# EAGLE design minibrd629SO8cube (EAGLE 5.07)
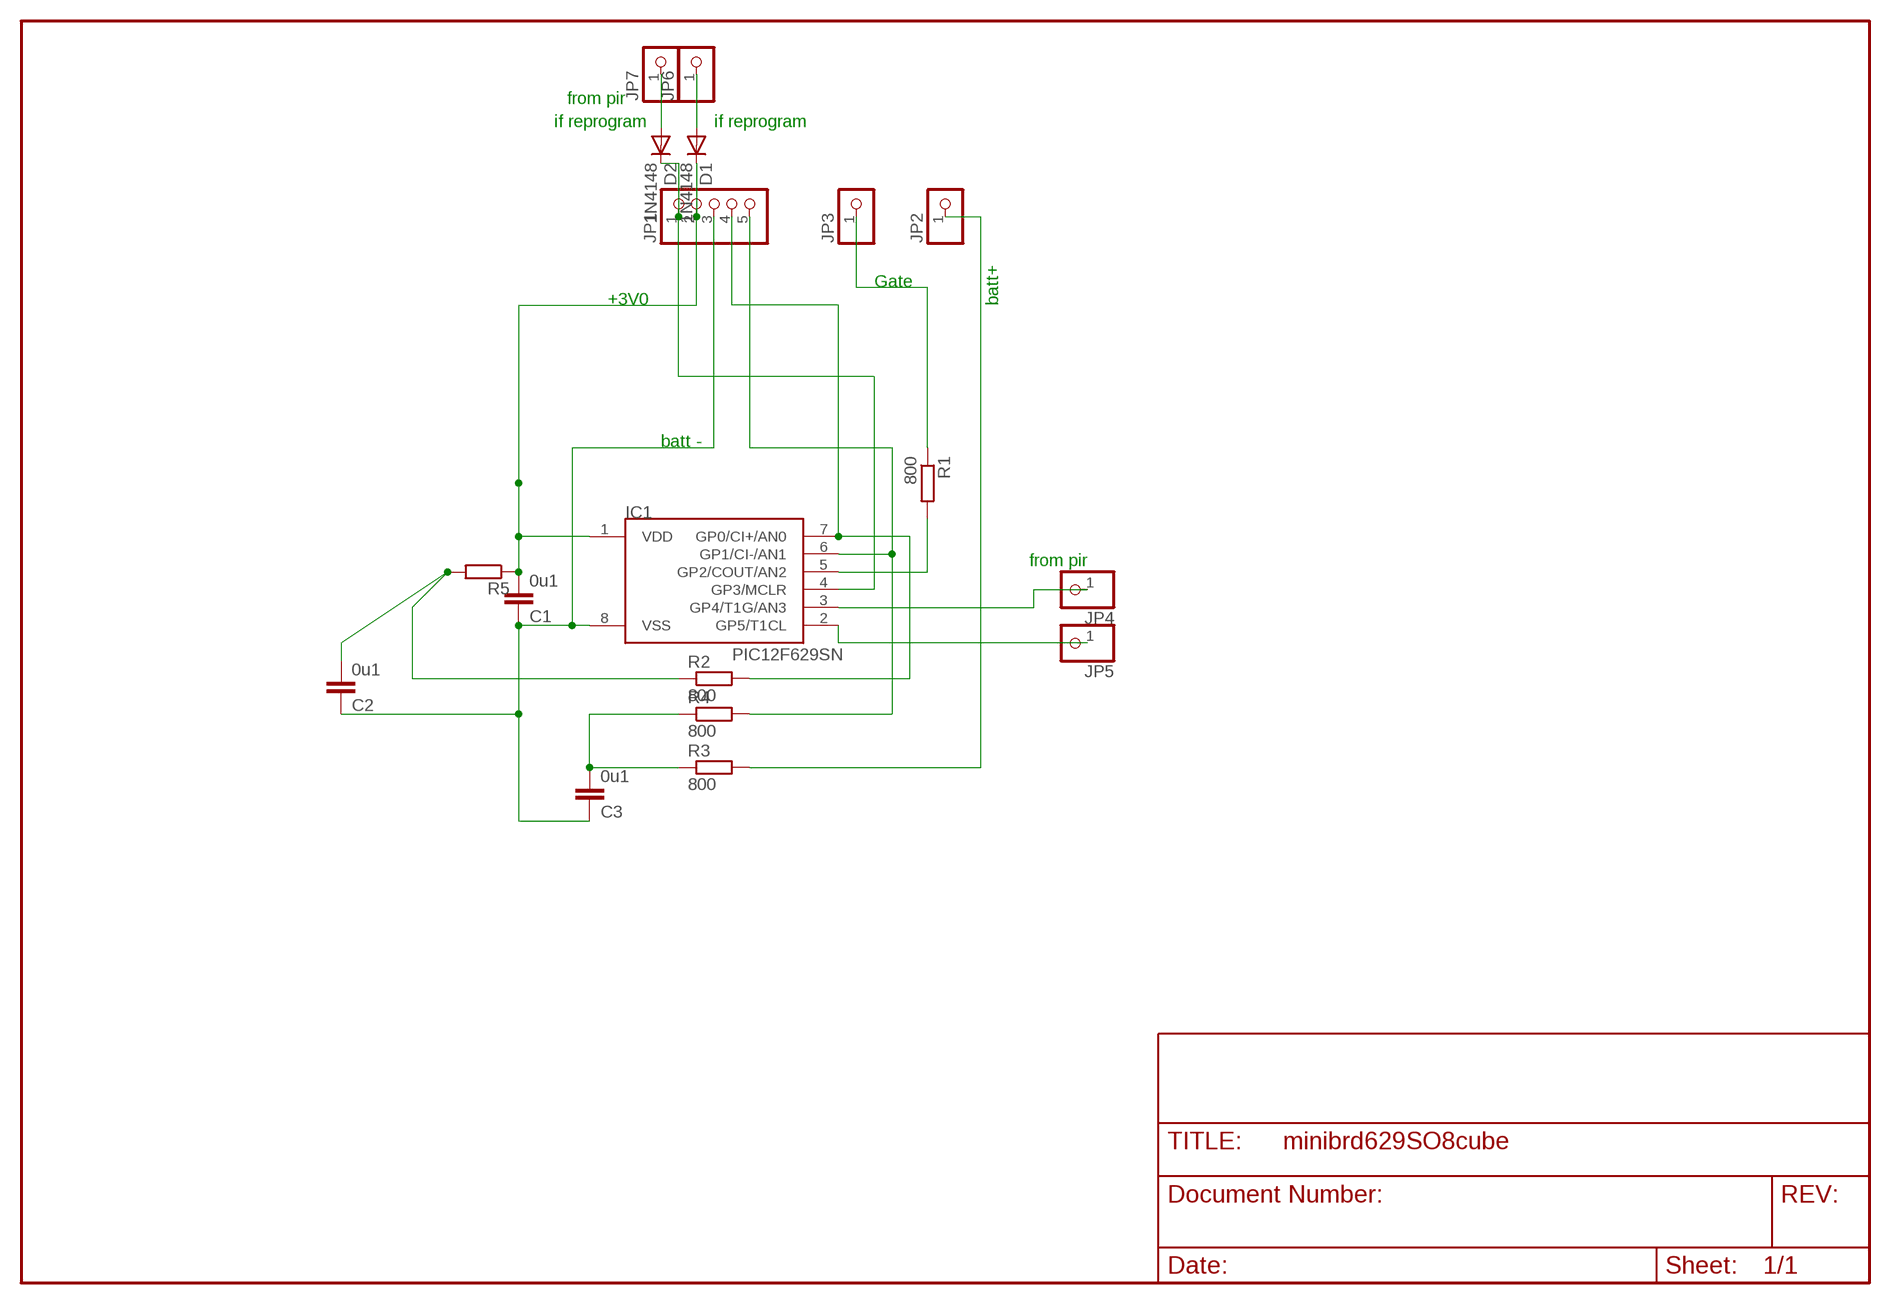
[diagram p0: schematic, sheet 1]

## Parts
C1  0u1  C-EUC1206  [C1206]
C2  0u1  C-EUC1206  [C1206]
C3  0u1  C-EUC1206  [C1206]
D1  1N4148  [DO35-10]
D2  1N4148  [DO35-10]
IC1  PIC12F629SN  [SO-08]
JP1  PINHD-1X5  [1X05]
JP2  PINHD-1X1  [1X01]
JP3  PINHD-1X1  [1X01]
JP4  PINHD-1X1  [1X01]
JP5  PINHD-1X1  [1X01]
JP6  PINHD-1X1  [1X01]
JP7  PINHD-1X1  [1X01]
R1  800  R-EU_M1206  [M1206]
R2  800  R-EU_M1206  [M1206]
R3  800  R-EU_M1206  [M1206]
R4  800  R-EU_M1206  [M1206]
R5  R-EU_0613/5V  [P0613V]

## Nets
N$1: IC1.5(GP2/COUT/AN2) R1.2
N$2: D2.A JP7.1
N$3: D1.A JP6.1
N$4: IC1.7(GP0/CI+/AN0) JP1.4 R2.2
N$5: JP3.1 R1.1
N$6: C2.2 R2.1 R5.2
N$7: C3.2 R3.1 R4.1
N$8: IC1.6(GP1/CI-/AN1) JP1.5 R4.2
N$13: IC1.3(GP4/T1G/AN3) JP4.1
N$14: IC1.2(GP5/T1CL) JP5.1
PIR: D2.C IC1.4(GP3/MCLR) JP1.1
V3: C1.2 D1.C IC1.1(VDD) JP1.2 R5.1
V+: JP2.1 R3.2
V-: C1.1 C2.1 C3.1 IC1.8(VSS) JP1.3

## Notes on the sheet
- from pir
- if reprogram | if reprogram
- Gate
- +3V0 | batt+
- batt -
- from pir

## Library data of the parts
C1-C3 = rcl:C-EU: CAPACITOR, European symbol
D1 D2 = diode-1:1N4148: DIODE
IC1 = microchip-3:PIC12F6*: uPC nW 1k Program Flash memory 2x Timer Comparator 10b A/D converter/ 4xIN
JP1 = pinhead:PINHD-1X5: PIN HEADER
JP2-JP7 = pinhead:PINHD-1X1: PIN HEADER
R1-R5 = rcl:R-EU_: RESISTOR, European symbol

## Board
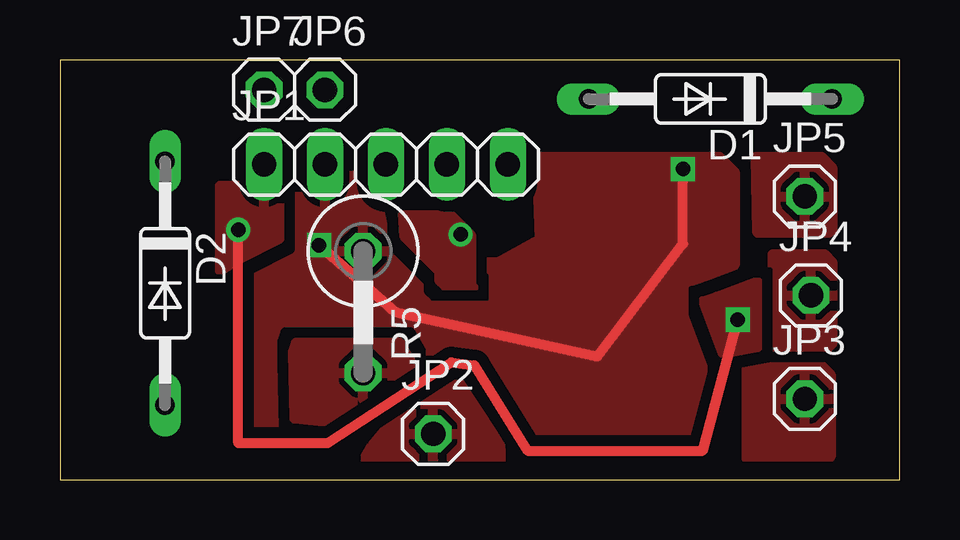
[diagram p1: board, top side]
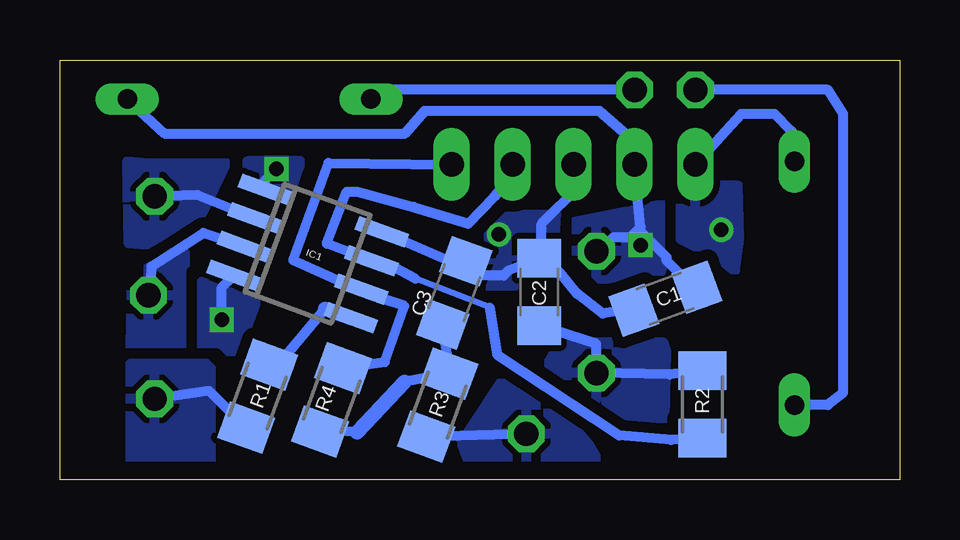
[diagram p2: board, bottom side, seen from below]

Size 35 x 17.5 mm. Coordinates in mm from the lower left corner, seen from the top.
Outline: 0,0 35,0 35,17.5 0,17.5 0,0
Copper layers (1*16): Top 0.035mm / dielectric 1.5mm / Bottom 0.035mm
Design rules "default *": minimum track width 10mil, minimum drill 24mil, track to track 18mil, track to pad 18mil, pad to pad 8mil, via to via 8mil, smd to smd 8mil, copper to edge 30mil, drill to drill 8mil, minimum pad ring 10mil, minimum via ring 8mil, stop-mask expansion 4mil, vias tented up to drill 0mil, thermal gap 10mil

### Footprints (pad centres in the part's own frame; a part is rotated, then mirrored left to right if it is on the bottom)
C1206 = smd 1.6 x 1.8: 1 -1.4,0; 2 1.4,0
DO35-10 = drill 0.813 long: A 5.08,0; C -5.08,0
SO-08 = smd 0.6 x 2.2: 1 -1.905,-2.6; 2 -0.635,-2.6; 3 0.635,-2.6; 4 1.905,-2.6; 5 1.905,2.6; 6 0.635,2.6; 7 -0.635,2.6; 8 -1.905,2.6
1X05 = drill 1.016 long: 1 -5.08,0; 2 -2.54,0; 3 0,0; 4 2.54,0; 5 5.08,0
1X01 = drill 1.016 octagon: 1 0,0
M1206 = smd 1.6 x 2: 1 -1.4,0; 2 1.4,0
P0613V = drill 1.016 octagon: 1 -2.54,0; 2 2.54,0

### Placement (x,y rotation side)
C1  9.76,7.54 20 bottom
C2  15.02,7.82 270 bottom
C3  18.56,7.79 250 bottom
D1  27.11,15.88 180 top
D2  4.38,8.19 270 top
IC1  24.67,9.43 250 bottom
JP1  13.59,13.14 0 top
JP2  15.56,1.91 0 top
JP3  31.05,3.37 0 top
JP4  31.31,7.68 0 top
JP5  31.05,11.81 0 top
JP6  11.05,16.26 0 top
JP7  8.51,16.26 0 top
R1  26.76,3.47 70 bottom
R2  8.22,3.14 270 bottom
R3  19.25,3.1 250 bottom
R4  23.67,3.33 70 bottom
R5  12.64,6.99 270 top

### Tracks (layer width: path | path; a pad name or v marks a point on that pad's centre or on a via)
N$1
  Bottom 0.406: R1.2 25.97,4.7 23.94,7.11
  Bottom 0.61: 23.94,7.11 IC1.5
N$2
  Bottom 0.406: D2.A 2.98,3.11 2.35,3.62 2.35,15.24 2.98,16.26 JP7.1
N$3
  Bottom 0.406: JP6.1 21.34,16.26 21.34,16.13 D1.A
N$4
  Bottom 0.254: 17.08,7.18 20.19,8.38
  Bottom 0.406: JP1.4 16,12.83 16.89,11.81 17.97,10.67 20.26,11.37 22.61,12 23.05,12 23.88,9.84 IC1.7 21.91,9.08 21.02,8.83 20.19,8.38 | 17.08,7.18 16.76,5.21 11.68,1.84 9.53,1.65 R2.2
N$5
  Bottom 0.406: R1.1 28.77,3.69 JP3.1
  pour Bottom: 28.89,4.83 32.07,4.83 32.07,0.76 28.7,0.76 28.7,4.64
  pour Top (rank 2): 28.64,4.7 31.81,4.7 32.13,4.38 32.13,0.95 31.94,0.76 28.7,0.76 28.64,0.83
N$6
  Bottom 0.406: R2.1 9.59,4.38 R5.2 12.64,5.65 C2.2
  pour Bottom: 9.84,5.71 14.16,5.71 14.73,4.7 10.99,2.41 9.78,2.54 9.72,5.33
  pour Top: 9.84,5.71 14.16,5.71 14.73,4.7 10.99,2.41 9.78,2.54 9.72,5.33
N$7
  Bottom 0.406: C3.2 18.73,4.32 R3.1 20.64,4.06 | R4.1 24,2.1 22.61,1.97
  Bottom 0.61: 20.64,4.06 22.61,1.97
N$8
  Bottom 0.406: JP1.5 23.81,13.21 25.27,9.14 23.05,8.13 22.54,7.87 | 22.54,7.87 IC1.6 | 22.54,7.87 20.64,7.24 21.46,4.89 23.3,4.64 R4.2
N$13
  Bottom 0.406: IC1.3 29.02,10.29 31.18,8.89 JP4.1
  pour Bottom (rank 3): 30.61,9.14 32,8.51 32.07,5.52 29.78,5.52 29.78,9.46
  pour Top (rank 3): 29.72,9.4 31.88,9.4 32.19,9.08 32.19,5.65 32.07,5.52 29.72,5.52 29.65,5.59
N$14
  Bottom 0.406: IC1.2 29.27,11.87 31.18,11.81 JP5.1
  pour Bottom: 28.07,13.21 29.08,11.11 31.43,9.78 32.13,9.84 32.19,13.27 31.24,13.21
  pour Top: 29.02,13.46 31.75,13.46 32.19,13.02 32.19,10.41 32.07,10.29 29.08,10.29
PIR  (via drill 0.6)
  Top 0.406: v7.43,10.41 7.43,1.52 11.18,1.52 16.32,4.89 17.27,4.76 19.49,1.21 26.8,1.21 v28.26,6.67
  Bottom 0.406: IC1.4 27.77,8.49 28.26,8 v28.26,6.67 | D2.C 4.51,14.54 5.21,15.24 6.6,15.24 JP1.1
  pour Bottom (rank 2): 26.8,7.43 27.62,5.27 29.08,5.52 29.08,8.26 27.37,7.62
  pour Bottom: 6.73,12.26 9.14,12.32 9.14,10.03 7.49,9.21 6.86,8.7 6.67,10.03
  pour Top: 26.8,7.43 27.62,5.27 29.08,5.52 29.08,8.26 27.37,7.62
  pour Top: 6.67,12.26 9.14,12.32 9.14,10.03 7.49,9.21 6.67,8.7
V3  (via drill 0.6)
  Top 0.406: v25.97,12.95 25.97,9.84 22.42,5.14 13.97,6.99 v10.79,9.78
  Bottom 0.406: IC1.1 26.46,12.46 v25.97,12.95 | 10.89,10.45 10.99,10.35 | 10.99,10.35 11.24,10.1 11.94,10.1 12.64,9.4 R5.1 | 10.89,10.45 10.8,10.54 JP1.2 11.05,14.1 12.51,15.37 19.81,15.37 20.64,14.41 30.61,14.41 D1.C | C1.2 8.59,8.02 9.72,9.14 9.72,9.27 10.89,10.45 | 10.89,10.45 | v10.79,9.78 10.79,10.16 10.99,10.35
  pour Bottom (rank 2): 25.34,12.13 24.96,13.27 27.18,13.27 27.3,12.76
  pour Bottom (rank 2): 9.91,11.49 9.91,8.7 12.45,8.32 13.65,9.53 13.65,10.73
  pour Top (rank 3): 19.88,13.46 27.5,13.46 28.13,12.83 28.13,8.95 27.94,8.76 27.62,8.76 27.88,0.57 18.86,0.7 13.91,6.41 11.75,6.41 11.05,0.95 6.99,0.95 7.18,11.43 12.95,12.89 13.72,9.27 18.29,9.08 20,10.03
V+
  Bottom 0.406: JP2.1 15.49,1.91 R3.2
  pour Bottom: 12.95,1.46 13.78,2.48 16.57,4.13 18.29,1.52 17.97,0.7 12.57,0.83
  pour Top: 13.02,1.4 13.84,2.41 16.64,4.06 18.35,1.46 18.41,0.38 12.45,0.44
V-  (via drill 0.6)
  Bottom 0.406: IC1.8 17.97,8.76 C3.1 18.08,9.06 17.53,8.51 16.51,8.51 16.3,8.71 C2.1 | JP1.3 13.33,12.26 14.92,10.67 14.92,8.89 15.1,8.71 C2.1 | C2.1 14.56,8.71 14.16,8.64 13.45,7.76 12.38,6.92 11.38,7.06 C1.1
  other vias: 16.7,10.22
  pour Bottom (isolate 0.406): 14.22,11.11 16.32,11.11 17.21,10.22 17.21,8.13 17.34,8 16,8 15.75,8.26 15.75,8.64 14.29,10.1
  pour Top (isolate 0.406): 14.22,11.11 16.32,11.11 17.21,10.22 17.21,8.13 17.34,8 16,8 15.75,8.26 15.75,8.64 14.29,10.1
